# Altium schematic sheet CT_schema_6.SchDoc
size 293 x 258 mm
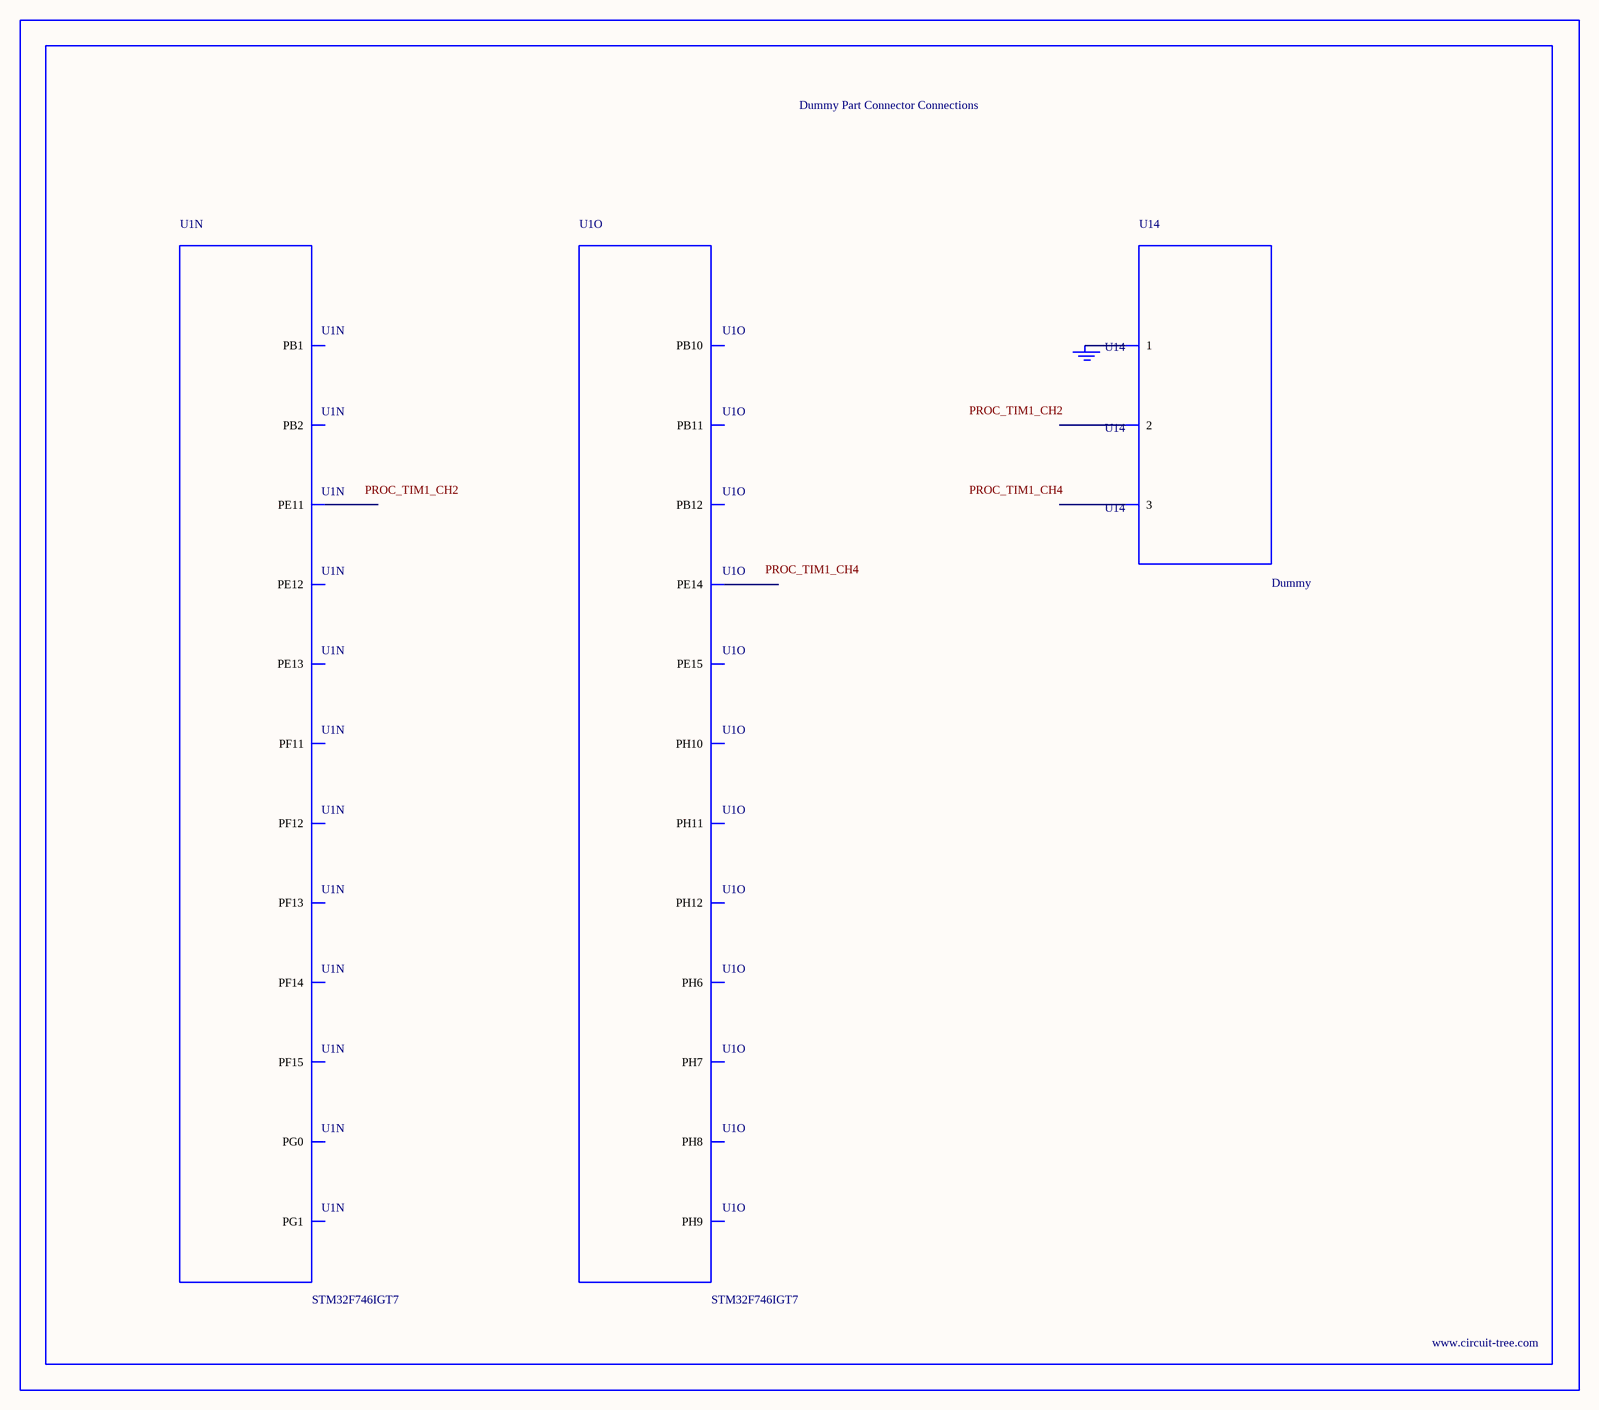
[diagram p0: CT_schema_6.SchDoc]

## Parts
BORDER5  (no value)
GND_INSTANCE_5_0  (no value)
U1  STM32F746IGT7  [LQFP176]  (parts N,O of 15)
U14  Dummy  [DUMMY_PACKAGE_191]

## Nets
NetGND_INSTANCE_5_0_0: GND_INSTANCE_5_0.0(GND) U14.1

Not connected (* = marked no-connect by the designer): U1 57(PB1) 58(PB2) 59(PF11) 60(PF12) 63(PF13) 64(PF14) 65(PF15) 66(PG0) 67(PG1) 74(PE11) 75(PE12) 76(PE13) 77(PE14) 78(PE15) 79(PB10) 80(PB11) 83(PH6) 84(PH7) 85(PH8) 86(PH9) 87(PH10) 88(PH11) 89(PH12) 92(PB12); U14 2 3

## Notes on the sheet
- Labels drawn without touching a wire or pin: PROC_TIM1_CH2, PROC_TIM1_CH4

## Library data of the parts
BORDER5 = BORDER_PAGE5
GND_INSTANCE_5_0 = GND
